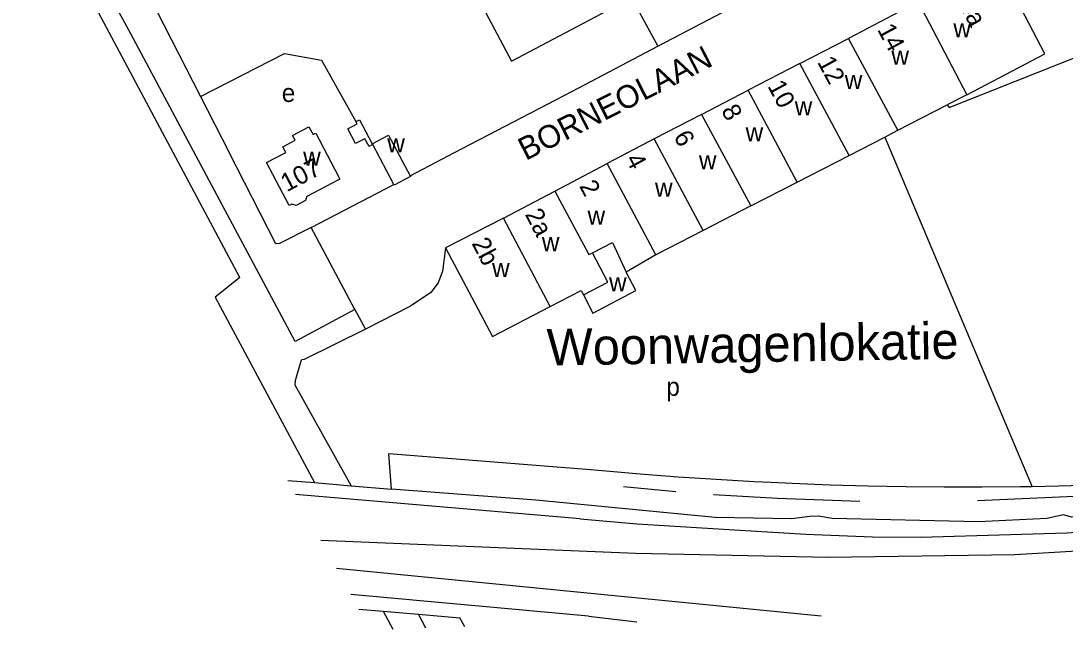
# Model space of a CAD drawing. Extents: x 162883 to 165538, y 383986 to 385172.
# Drawn here: x 162930.3 to 163159.5, y 383986.5 to 384119.8 of the extents above; entities that cross this region are included whole.
import ezdxf

# ---------------------------------------------------------------- set-up
doc = ezdxf.new("R2010")
doc.units = 0
for name, color, linetype in [('BLT_Basislijn', 7, 'Continuous'), ('BLT_Bebouwing', 7, 'Continuous'), ('BLT_Centroide', 7, 'Continuous'), ('BLT_Huisnummer', 7, 'Continuous'), ('BLT_Huisnummer_ tussenligend', 7, 'Continuous'), ('BLT_Spoorlijn', 7, 'Continuous'), ('BLT_Straatnaam', 7, 'Continuous'), ('BLT_Terrein_beschrifting', 7, 'Continuous'), ('BLT_Vlakafsluiter', 7, 'Continuous')]:
    doc.layers.add(name, color=color, linetype=linetype)

msp = doc.modelspace()

# ---------------------------------------------------------------- linework, layer by layer
at = {"layer": 'BLT_Basislijn'}
for p, q in [((162942.96, 384155.66), (162969.69, 384103.29)), ((162978.36, 384063.54), (162930.26, 384153.6)), ((163064.31, 384124.97), (163070.12, 384114.29)), ((163070.12, 384114.29), (163086.07, 384122.62)), ((163127.21, 384124.05), (163111.93, 384116)), ((163127.21, 384124.05), (163137.93, 384103.6)), ((163101.28, 384110.49), (163111.93, 384116)), ((163122.78, 384095.85), (163111.93, 384116)), ((163052.74, 384105.2), (163070.12, 384114.29)), ((162969.69, 384103.29), (162988.1, 384112.71)), ((163101.28, 384110.49), (163089.93, 384104.62)), ((163112.09, 384090.36), (163101.28, 384110.49)), ((163047.7, 384102.57), (163052.74, 384105.2)), ((163079.66, 384099.3), (163089.93, 384104.62)), ((163100.68, 384084.5), (163089.93, 384104.62)), ((162969.69, 384103.29), (162975.89, 384091.14)), ((163025.48, 384090.96), (163047.7, 384102.57)), ((163137.93, 384103.6), (163133.61, 384101.41)), ((163079.66, 384099.3), (163069.31, 384093.95)), ((163079.66, 384099.3), (163090.49, 384079.27)), ((163119.89, 384094.36), (163122.78, 384095.85)), ((163069.31, 384093.95), (163058.95, 384088.59)), ((163080.01, 384073.89), (163069.31, 384093.95)), ((163112.09, 384090.36), (163119.89, 384094.36)), ((163119.89, 384094.36), (163136.48, 384055.07)), ((163015.7, 384085.85), (163025.48, 384090.96)), ((163100.68, 384084.5), (163112.09, 384090.36)), ((163047.46, 384082.49), (163058.95, 384088.59)), ((163069.63, 384068.56), (163058.95, 384088.59)), ((162994.02, 384074.54), (163012.13, 384083.98)), ((163090.49, 384079.27), (163100.68, 384084.5)), ((163036.21, 384076.59), (163047.46, 384082.49)), ((163090.49, 384079.27), (163080.01, 384073.89)), ((163036.21, 384076.59), (163023.47, 384070.08)), ((163046.47, 384057.2), (163036.21, 384076.59)), ((163003.54, 384056.54), (162994.02, 384074.54)), ((163080.01, 384073.89), (163069.63, 384068.56)), ((163069.63, 384068.56), (163063.15, 384064.76)), ((162972.9, 384059.25), (162994.74, 384018.59)), ((163003.54, 384056.54), (162990.47, 384049.56)), ((163003.54, 384056.54), (163005.89, 384052.23)), ((163136.48, 384055.07), (163152.27, 384017.7)), ((162990.46, 384040.75), (162991.84, 384045.51)), ((163054.46, 384021.48), (163011, 384024.9)), ((163011.62, 384017.19), (163011, 384024.9)), ((162988.85, 384019.07), (162994.74, 384018.59)), ((162994.74, 384018.59), (163002.78, 384017.92)), ((163002.78, 384017.92), (163011.62, 384017.19)), ((163062.57, 384017.77), (163074.01, 384016.68)), ((163004.46, 383990.86), (163009.82, 383990.39)), ((163009.82, 383990.39), (163017.54, 383989.73)), ((163017.54, 383989.73), (163026.64, 383988.95)), ((163027.69, 383986.95), (163026.64, 383988.95))]:
    msp.add_line(p, q, dxfattribs=at)
for points in [[(162990.47, 384049.56), (162954.42, 384117.02), (162933.9, 384154.67)], [(163054.76, 384142.52), (163028.58, 384128.68), (163037.94, 384111.04), (163064.31, 384124.97)], [(163133.61, 384101.41), (163134.07, 384100.88), (163177.74, 384118.17), (163177.9, 384118.33), (163177.62, 384125.28), (163223.64, 384141.61)], [(163137.93, 384103.6), (163155.03, 384112.62), (163144.43, 384133.05)], [(162988.1, 384112.71), (162996.28, 384111.21), (163003.81, 384097.75)], [(163640.05, 384101.58), (163588.66, 384090.3), (163570.6, 384086.32), (163483.78, 384068.15), (163420.83, 384054.89), (163311.71, 384032.16), (163269.21, 384023.98), (163233.89, 384018.31), (163209.6, 384015.27), (163207.84, 384015.67), (163204.36, 384014.69), (163187.71, 384012.5), (163168.11, 384011.42), (163160.93, 384011.03), (163159.13, 384011.52), (163155.45, 384010.73), (163140.49, 384010), (163108.38, 384010.73), (163105.35, 384011.23), (163103.45, 384011.19), (163099.49, 384010.63), (163082.66, 384010.93), (163043.27, 384014.78), (163011.62, 384017.19)], [(163122.78, 384095.85), (163133.61, 384101.41)], [(162994.02, 384074.54), (162987.05, 384071.01), (162986.22, 384070.98), (162975.89, 384091.14)], [(163047.46, 384082.49), (163054.91, 384068.6), (163055.73, 384069.01)], [(163023.47, 384070.08), (163022.85, 384064.97), (163021.84, 384062.41), (163020.24, 384060.29), (163015.79, 384057.32), (163005.89, 384052.23)], [(163023.47, 384070.08), (163033.76, 384050.61), (163046.47, 384057.2)], [(163046.47, 384057.2), (163053.23, 384060.76), (163053.76, 384059.74)], [(163140.24, 384014.65), (163173.07, 384016.12), (163206.5, 384018.84), (163244.56, 384023.67), (163270.13, 384028.54), (163326.53, 384040.14), (163382.74, 384051.7), (163417.38, 384058.65)], [(163005.89, 384052.23), (162992.44, 384045.59), (162991.84, 384045.51)], [(162990.46, 384040.75), (162990.43, 384040.02), (163002.78, 384017.92)], [(163094.86, 384018.59), (163091.21, 384018.77), (163082.87, 384019.25), (163074.54, 384019.8), (163066.21, 384020.44), (163057.89, 384021.16), (163054.46, 384021.48)], [(163152.27, 384017.7), (163149.67, 384017.65), (163141.31, 384017.57), (163132.96, 384017.57), (163124.61, 384017.65), (163116.25, 384017.81), (163107.9, 384018.05), (163099.56, 384018.37), (163094.86, 384018.59)], [(163174.71, 384018.37), (163166.37, 384018.05), (163158.02, 384017.81), (163152.27, 384017.7)], [(163082.33, 384015.96), (163096.38, 384015.21), (163114.45, 384014.55)], [(163009.82, 383990.39), (163011.93, 383986.48)], [(163019.15, 383986.7), (163017.54, 383989.73)]]:
    msp.add_lwpolyline(points, dxfattribs=at)
at = {"layer": 'BLT_Bebouwing'}
for points in [[(163012.13, 384083.98), (163007.5, 384092.72), (163006.69, 384092.29), (163005.78, 384094.02), (163003.75, 384092.94), (163002.03, 384096.19), (163004.07, 384097.27), (163003.81, 384097.75)], [(163003.81, 384097.75), (163004.61, 384098.17), (163007.4, 384092.91), (163010.96, 384094.8), (163015.7, 384085.85)], [(163000, 384085.73), (163000.3, 384085.17), (163000, 384085.01), (162993.01, 384081.35), (162992.73, 384080.44), (162990.72, 384079.38), (162989.76, 384079.68), (162989.16, 384079.36), (162984.18, 384088.79), (162988.41, 384091.02), (162987.76, 384092.26), (162990.44, 384093.68), (162989.89, 384094.72), (162993.51, 384096.63), (162994.41, 384094.93), (162994.99, 384095.24), (163000, 384085.73)], [(163015.7, 384085.85), (163015.76, 384085.73), (163012.21, 384083.85), (163012.13, 384083.98)], [(163055.73, 384069.01), (163060.1, 384071.23), (163063.15, 384064.76)], [(163053.76, 384059.74), (163059.14, 384062.55), (163055.73, 384069.01)], [(163053.76, 384059.74), (163055.85, 384055.77), (163065.27, 384060.74), (163063.15, 384064.76)]]:
    msp.add_lwpolyline(points, dxfattribs=at)
at = {"layer": 'BLT_Spoorlijn'}
for points in [[(163053.01, 384010.69), (162990.56, 384015.97)], [(163053.01, 384010.69), (163065.54, 384009.55), (163083.35, 384008.43), (163102.56, 384007.32), (163117.19, 384006.73), (163127.77, 384006.66), (163159.89, 384007.57), (163190.5, 384009.82), (163208.59, 384011.77), (163239.03, 384015.08)], [(162996.1, 384005.96), (163065.22, 384003.16), (163107.56, 384002.23), (163148.48, 384002.82), (163191.87, 384005.42), (163229.43, 384009.69)], [(163105.98, 383989.31), (162999.54, 383999.74)], [(163054.88, 383989.32), (163002.67, 383994.09)], [(163054.88, 383989.32), (163065.49, 383988.09)]]:
    msp.add_lwpolyline(points, dxfattribs=at)
at = {"layer": 'BLT_Vlakafsluiter'}
msp.add_line((162978.36, 384063.54), (162972.9, 384059.25), dxfattribs=at)

# ---------------------------------------------------------------- texts
at = {"layer": 'BLT_Centroide'}
for s, p in [('w', (163134.96, 384116.25)), ('w', (163121.36, 384110.23)), ('w', (163111.12, 384104.92)), ('e', (162987.53, 384102.06)), ('w', (163100.14, 384099.16)), ('w', (163089.36, 384093.45)), ('w', (163010.69, 384091)), ('w', (162992.23, 384088.08)), ('w', (163079.11, 384087.3)), ('w', (163069.47, 384081.27)), ('w', (163054.66, 384075.17)), ('w', (163044.63, 384069.35)), ('w', (163033.7, 384063.67)), ('w', (163059.38, 384060.54)), ('p', (163071.95, 384037.63))]:
    msp.add_text(s, height=4, dxfattribs=at).set_placement(p)
at = {"layer": 'BLT_Huisnummer'}
for s, rotation, p in [('14a', 298.3021, (163134.63, 384126.08)), ('14', 298.3021, (163118.18, 384117.96)), ('10', 298.3021, (163094.08, 384105.56)), ('6', 298.3021, (163073.46, 384094.51)), ('107', 27.6751, (162988.62, 384082.24)), ('2', 298.3021, (163052.75, 384083.64)), ('2a', 297.598, (163040.84, 384077.45)), ('2b', 297.598, (163029.15, 384071.07))]:
    msp.add_text(s, height=4, rotation=rotation, dxfattribs=at).set_placement(p)
at = {"layer": 'BLT_Huisnummer_ tussenligend'}
for s, p in [('12', (163105.01, 384110.82)), ('8', (163083.91, 384100.21)), ('4', (163062.89, 384089.52))]:
    msp.add_text(s, height=4, rotation=298.3021, dxfattribs=at).set_placement(p)
at = {"layer": 'BLT_Straatnaam'}
msp.add_text('BORNEOLAAN', height=5, rotation=26.9327, dxfattribs=at).set_placement((163041.09, 384089.11))
at = {"layer": 'BLT_Terrein_beschrifting'}
msp.add_text('Woonwagenlokatie', height=8, rotation=0.9629, dxfattribs=at).set_placement((163045.77, 384044.25))

doc.saveas('drawing.dxf')
